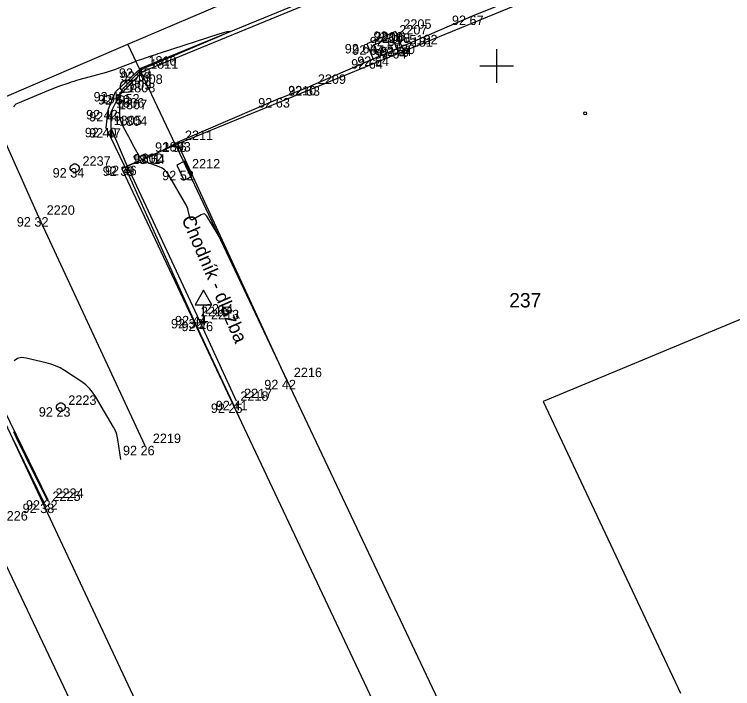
# Model space of a CAD drawing. Extents: x -711081 to -709338, y -1025122 to -1024092.
# Drawn here: x -710739.27 to -710718.02, y -1024943.41 to -1024923.47 of the extents above; entities that cross this region are included whole.
import ezdxf

# ---------------------------------------------------------------- set-up
doc = ezdxf.new("R2010")
doc.units = 0
for name, color, linetype in [('Ex_Minor Contours', 7, 'Continuous'), ('Z_bodove_pole', 7, 'Continuous'), ('Z_bodove_pole_cisla', 7, 'Continuous'), ('Z_bodove_pole_vysky', 7, 'Continuous'), ('Z_body', 7, 'Continuous'), ('Z_body_cisla', 7, 'Continuous'), ('Z_body_vysky_redukovane', 7, 'Continuous'), ('Z_budova', 7, 'Continuous'), ('Z_dopravni_znacky', 7, 'Continuous'), ('Z_hektometricka_sit', 7, 'Continuous'), ('Z_katastr_cisla_stavebni', 7, 'Continuous'), ('Z_katastr_hranice', 7, 'Continuous'), ('Z_katastr_vnitrni_kresba', 7, 'Continuous'), ('Z_katastr_znacky_budov', 7, 'Continuous'), ('Z_komunikace', 7, 'Continuous'), ('Z_komunikace_osa', 7, 'Continuous'), ('Z_obruba', 7, 'Continuous'), ('Z_pilire', 7, 'Continuous'), ('Z_popisy', 7, 'Continuous'), ('Z_rozhranni', 7, 'Continuous'), ('Z_site_vodovod_znaky', 7, 'Continuous'), ('Z_vstupy', 7, 'Continuous')]:
    doc.layers.add(name, color=color, linetype=linetype)

# ---------------------------------------------------------------- blocks, each defined once
blk = doc.blocks.new('POINT_DISPLAY')
blk.add_line((0, 0), (0, 0))
blk = doc.blocks.new('Z666')
for p, q in [((-0.25, 0.13), (-0.25, -0.13)), ((0.25, 0.13), (-0.25, 0.13)), ((0.25, -0.13), (0.25, 0.13)), ((-0.25, -0.13), (0.25, -0.13))]:
    blk.add_line(p, q)
blk = doc.blocks.new('Z614')
for p, q in [((-0.13, 0.03), (-0.1, 0.08)), ((-0.13, -0.03), (-0.13, 0.03)), ((-0.1, 0.08), (-0.08, 0.1)), ((-0.08, 0.1), (-0.03, 0.13)), ((-0.03, 0.13), (0.03, 0.13)), ((0.03, 0.13), (0.08, 0.1)), ((0.08, 0.1), (0.1, 0.08)), ((0.1, 0.08), (0.13, 0.03)), ((0.13, 0.03), (0.13, -0.03)), ((-0.1, -0.08), (-0.13, -0.03)), ((-0.08, -0.1), (-0.1, -0.08)), ((-0.03, -0.13), (-0.08, -0.1)), ((0.03, -0.13), (-0.03, -0.13)), ((0.08, -0.1), (0.03, -0.13)), ((0.1, -0.08), (0.08, -0.1)), ((0.13, -0.03), (0.1, -0.08))]:
    blk.add_line(p, q)
blk = doc.blocks.new('Z527')
for p, q in [((0, 0.93), (-0.25, 0.5)), ((0.25, 0.5), (0, 0.93)), ((-0.25, 0.5), (0.25, 0.5)), ((0, 0), (0, 0.5)), ((-0.13, 0), (0.13, 0))]:
    blk.add_line(p, q)
blk = doc.blocks.new('Z101')
for radius in [0.188, 0.0025]:
    blk.add_circle((0, 0), radius)

msp = doc.modelspace()

# ---------------------------------------------------------------- linework, layer by layer
at = {"layer": 'Ex_Minor Contours'}
for points in [[(-710733.066, -1024930.269), (-710733.573, -1024929.439), (-710733.607, -1024929.398), (-710733.646, -1024929.377), (-710733.69, -1024929.378), (-710733.74, -1024929.399), (-710733.959, -1024929.532), (-710734, -1024929.549), (-710734.033, -1024929.547), (-710734.058, -1024929.525), (-710734.074, -1024929.483), (-710734.121, -1024929.276), (-710734.135, -1024929.225), (-710734.152, -1024929.175), (-710734.174, -1024929.127), (-710734.199, -1024929.081), (-710734.707, -1024928.214), (-710734.76, -1024928.138), (-710734.824, -1024928.074), (-710734.897, -1024928.022), (-710734.981, -1024927.983), (-710735.353, -1024927.841), (-710735.429, -1024927.805), (-710735.495, -1024927.757), (-710735.551, -1024927.698), (-710735.597, -1024927.628), (-710735.768, -1024927.31), (-710735.805, -1024927.24), (-710735.843, -1024927.17), (-710735.88, -1024927.1), (-710735.917, -1024927.03), (-710736.066, -1024926.75), (-710736.098, -1024926.679), (-710736.122, -1024926.605), (-710736.138, -1024926.53), (-710736.144, -1024926.452), (-710736.158, -1024925.921), (-710736.157, -1024925.891), (-710736.152, -1024925.862), (-710736.142, -1024925.834), (-710736.129, -1024925.807), (-710736.066, -1024925.701), (-710736.049, -1024925.676), (-710736.031, -1024925.651), (-710736.012, -1024925.627), (-710735.991, -1024925.604), (-710735.787, -1024925.394), (-710735.758, -1024925.364), (-710735.73, -1024925.335), (-710735.702, -1024925.306), (-710735.673, -1024925.276), (-710735.56, -1024925.159), (-710735.531, -1024925.131), (-710735.499, -1024925.107), (-710735.465, -1024925.086), (-710735.428, -1024925.068), (-710733.193, -1024924.12), (-710732.967, -1024924.02), (-710732.895, -1024923.978), (-710732.977, -1024923.992), (-710733.214, -1024924.064), (-710734.957, -1024924.623), (-710735.026, -1024924.645), (-710735.094, -1024924.667), (-710735.162, -1024924.69), (-710735.23, -1024924.713), (-710735.503, -1024924.805), (-710735.571, -1024924.828), (-710735.638, -1024924.853), (-710735.706, -1024924.878), (-710735.773, -1024924.904), (-710736.184, -1024925.069), (-710736.275, -1024925.104), (-710736.367, -1024925.136), (-710736.46, -1024925.166), (-710736.554, -1024925.193), (-710737.356, -1024925.412), (-710737.432, -1024925.433), (-710737.508, -1024925.456), (-710737.583, -1024925.48), (-710737.658, -1024925.506), (-710737.956, -1024925.611), (-710738.03, -1024925.638), (-710738.104, -1024925.666), (-710738.178, -1024925.695), (-710738.251, -1024925.725), (-710739.169, -1024926.106), (-710739.217, -1024926.132), (-710739.257, -1024926.165), (-710739.289, -1024926.206)], [(-710736.118, -1024936.633), (-710736.202, -1024936.046), (-710736.22, -1024935.949), (-710736.248, -1024935.856), (-710736.285, -1024935.766), (-710736.33, -1024935.68), (-710736.867, -1024934.771), (-710736.95, -1024934.647), (-710737.046, -1024934.534), (-710737.154, -1024934.432), (-710737.274, -1024934.343), (-710737.783, -1024934.007), (-710737.911, -1024933.93), (-710738.045, -1024933.865), (-710738.184, -1024933.813), (-710738.328, -1024933.773), (-710738.914, -1024933.635), (-710739.051, -1024933.622), (-710739.168, -1024933.651), (-710739.267, -1024933.721)], [(-710739.293, -1024935.803), (-710739.208, -1024935.986), (-710739.121, -1024936.168), (-710739.034, -1024936.35), (-710738.945, -1024936.531), (-710738.289, -1024937.859)]]:
    msp.add_lwpolyline(points, dxfattribs=at)
at = {"layer": 'Z_budova'}
for p, q in [((-710717.04, -1024920.03), (-710725.67, -1024923.51)), ((-710725.67, -1024923.51), (-710730.51, -1024925.6)), ((-710731.4, -1024925.95), (-710734.45, -1024927.26)), ((-710734.45, -1024927.26), (-710731.22, -1024934.28))]:
    msp.add_line(p, q, dxfattribs=at)
at = {"layer": 'Z_hektometricka_sit'}
for p, q in [((-710725, -1024924.5), (-710725, -1024925.5)), ((-710725.5, -1024925), (-710724.5, -1024925))]:
    msp.add_line(p, q, dxfattribs=at)
at = {"layer": 'Z_katastr_hranice'}
for p, q in [((-710735.91, -1024924.36), (-710698.09, -1024908.18)), ((-710717.1, -1024920.2), (-710734.5, -1024927.33)), ((-710744.84, -1024928.18), (-710735.91, -1024924.36)), ((-710734.5, -1024927.33), (-710735.91, -1024924.36)), ((-710734.5, -1024927.33), (-710734.37, -1024927.6)), ((-710734.37, -1024927.6), (-710725.49, -1024946.36)), ((-710737.04, -1024944.96), (-710740.05, -1024938.63))]:
    msp.add_line(p, q, dxfattribs=at)
at = {"layer": 'Z_katastr_vnitrni_kresba'}
for p, q in [((-710734.5, -1024927.33), (-710736.09, -1024928.04)), ((-710736.09, -1024928.04), (-710710.637, -1024981.933)), ((-710712.55, -1024930.31), (-710723.62, -1024934.92)), ((-710741.85, -1024930.64), (-710716.679, -1024984.248)), ((-710723.62, -1024934.92), (-710719.56, -1024943.54))]:
    msp.add_line(p, q, dxfattribs=at)
at = {"layer": 'Z_katastr_znacky_budov'}
msp.add_circle((-710722.382, -1024926.4), 0.0437, dxfattribs=at)
at = {"layer": 'Z_komunikace'}
for p, q in [((-710735.52, -1024925.07), (-710726.72, -1024921.45)), ((-710736.27, -1024925.77), (-710735.52, -1024925.07)), ((-710736.49, -1024926.3), (-710736.27, -1024925.77)), ((-710736.55, -1024926.83), (-710736.49, -1024926.3)), ((-710736, -1024927.97), (-710736.55, -1024926.83)), ((-710736, -1024927.97), (-710733.98, -1024932.48)), ((-710738.27, -1024937.84), (-710741.84, -1024930.52)), ((-710733.98, -1024932.48), (-710732.8, -1024934.98))]:
    msp.add_line(p, q, dxfattribs=at)
at = {"layer": 'Z_komunikace_osa'}
for p, q in [((-710738.54, -1024929.47), (-710740.73, -1024924.63)), ((-710735.4, -1024936.23), (-710738.54, -1024929.47))]:
    msp.add_line(p, q, dxfattribs=at)
at = {"layer": 'Z_obruba'}
for p, q in [((-710735.47, -1024925.16), (-710726.67, -1024921.55)), ((-710736.16, -1024925.86), (-710735.47, -1024925.16)), ((-710736.4, -1024926.36), (-710736.16, -1024925.86)), ((-710736.4, -1024926.84), (-710736.4, -1024926.36)), ((-710735.93, -1024927.95), (-710736.4, -1024926.84)), ((-710735.93, -1024927.95), (-710733.86, -1024932.39)), ((-710738.37, -1024937.94), (-710741.97, -1024930.6)), ((-710733.86, -1024932.39), (-710732.7, -1024934.9))]:
    msp.add_line(p, q, dxfattribs=at)
at = {"layer": 'Z_rozhranni'}
for p, q in [((-710727.99, -1024923.98), (-710728.84, -1024924.35)), ((-710727.99, -1024923.98), (-710727.8, -1024924.43)), ((-710728.1, -1024924.14), (-710728.62, -1024924.39)), ((-710728.1, -1024924.14), (-710727.95, -1024924.5)), ((-710728.84, -1024924.35), (-710728.65, -1024924.8)), ((-710728.62, -1024924.39), (-710728.47, -1024924.72)), ((-710735.1, -1024927.61), (-710734.45, -1024927.26)), ((-710735.93, -1024927.95), (-710735.1, -1024927.61))]:
    msp.add_line(p, q, dxfattribs=at)
at = {"layer": 'Z_vstupy'}
msp.add_line((-710731.4, -1024925.95), (-710730.51, -1024925.6), dxfattribs=at)

# ---------------------------------------------------------------- block references
at = {"layer": 'Z_bodove_pole'}
msp.add_blockref('Z101', (-710735.94, -1024925.6), dxfattribs=at)
at = {"layer": 'Z_body'}
for p in [(-710725.67, -1024923.51), (-710727.99, -1024923.98), (-710728.1, -1024924.14), (-710728.84, -1024924.35), (-710728.62, -1024924.39), (-710727.95, -1024924.5), (-710727.8, -1024924.43), (-710728.47, -1024924.72), (-710728.65, -1024924.8), (-710735.52, -1024925.07), (-710735.47, -1024925.16), (-710735.94, -1024925.6), (-710730.51, -1024925.6), (-710736.27, -1024925.77), (-710736.16, -1024925.86), (-710731.4, -1024925.95), (-710736.49, -1024926.3), (-710736.4, -1024926.36), (-710736.55, -1024926.83), (-710736.4, -1024926.84), (-710734.45, -1024927.26), (-710735.1, -1024927.61), (-710735.93, -1024927.95), (-710737.48, -1024928.02), (-710736, -1024927.97), (-710734.24, -1024928.1), (-710738.54, -1024929.47), (-710733.86, -1024932.39), (-710733.98, -1024932.48), (-710733.67, -1024932.56), (-710731.22, -1024934.28), (-710732.7, -1024934.9), (-710737.89, -1024935.09), (-710732.8, -1024934.98), (-710735.4, -1024936.23), (-710738.37, -1024937.94), (-710738.27, -1024937.84)]:
    msp.add_blockref('POINT_DISPLAY', p, dxfattribs=at)
at = {"layer": 'Z_dopravni_znacky'}
msp.add_blockref('Z527', (-710733.67, -1024932.56), dxfattribs=at)
at = {"layer": 'Z_pilire', "rotation": -64.8}
msp.add_blockref('Z666', (-710734.24, -1024928.1), dxfattribs=at)
at = {"layer": 'Z_site_vodovod_znaky'}
for p in [(-710737.48, -1024928.02), (-710737.89, -1024935.09)]:
    msp.add_blockref('Z614', p, dxfattribs=at)

# ---------------------------------------------------------------- texts
at = {"layer": 'Z_bodove_pole_cisla'}
msp.add_text('4008', height=0.28, dxfattribs=at).set_placement((-710735.71, -1024925.53))
at = {"layer": 'Z_bodove_pole_vysky'}
msp.add_text('192,52', height=0.28, dxfattribs=at).set_placement((-710736.707, -1024926.11))
at = {"layer": 'Z_body_cisla'}
for s, p in [('2205', (-710727.76, -1024923.9)), ('2207', (-710727.88, -1024924.07)), ('2206', (-710728.61, -1024924.28)), ('2208', (-710728.39, -1024924.32)), ('5182', (-710727.58, -1024924.36)), ('5181', (-710727.72, -1024924.43)), ('5179', (-710728.42, -1024924.73)), ('5180', (-710728.25, -1024924.65)), ('1810', (-710735.3, -1024924.99)), ('1811', (-710735.25, -1024925.08)), ('2209', (-710730.29, -1024925.53)), ('1809', (-710736.05, -1024925.7)), ('1808', (-710735.93, -1024925.78)), ('2210', (-710731.17, -1024925.87)), ('1806', (-710736.26, -1024926.23)), ('1807', (-710736.17, -1024926.28)), ('1805', (-710736.33, -1024926.75)), ('1804', (-710736.17, -1024926.77)), ('2211', (-710734.22, -1024927.19)), ('1803', (-710734.88, -1024927.53)), ('2237', (-710737.25, -1024927.95)), ('1801', (-710735.78, -1024927.9)), ('1802', (-710735.71, -1024927.87)), ('2212', (-710734.01, -1024928.03)), ('2220', (-710738.31, -1024929.4)), ('2215', (-710733.75, -1024932.4)), ('2214', (-710733.63, -1024932.32)), ('2213', (-710733.45, -1024932.49)), ('2216', (-710731, -1024934.2)), ('2217', (-710732.47, -1024934.82)), ('2223', (-710737.67, -1024935.02)), ('2218', (-710732.58, -1024934.9)), ('2219', (-710735.17, -1024936.15)), ('2224', (-710738.05, -1024937.77)), ('2225', (-710738.14, -1024937.86)), ('2226', (-710739.7, -1024938.44))]:
    msp.add_text(s, height=0.28, dxfattribs=at).set_placement(p)
at = {"layer": 'Z_body_vysky_redukovane'}
for s, p in [('92 67', (-710726.323, -1024923.79)), ('92 66', (-710728.643, -1024924.26)), ('92 64', (-710729.493, -1024924.63)), ('92 64', (-710728.753, -1024924.42)), ('92 64', (-710729.273, -1024924.67)), ('92 64', (-710728.603, -1024924.78)), ('92 64', (-710728.453, -1024924.71)), ('92 64', (-710729.123, -1024925)), ('92 64', (-710729.303, -1024925.08)), ('92 48', (-710736.173, -1024925.35)), ('92 54', (-710736.123, -1024925.44)), ('92 63', (-710731.163, -1024925.88)), ('92 45', (-710736.923, -1024926.05)), ('92 50', (-710736.79, -1024926.14)), ('92 63', (-710732.053, -1024926.23)), ('92 42', (-710737.143, -1024926.58)), ('92 49', (-710737.053, -1024926.64)), ('92 40', (-710737.18, -1024927.11)), ('92 47', (-710737.053, -1024927.12)), ('92 56', (-710735.103, -1024927.54)), ('92 54', (-710735.753, -1024927.89)), ('92 46', (-710736.583, -1024928.23)), ('92 34', (-710738.133, -1024928.3)), ('92 39', (-710736.653, -1024928.25)), ('92 52', (-710734.893, -1024928.38)), ('92 32', (-710739.193, -1024929.75)), ('92 44', (-710734.513, -1024932.67)), ('92 32', (-710734.633, -1024932.76)), ('92 46', (-710734.323, -1024932.84)), ('92 42', (-710731.873, -1024934.56)), ('92 41', (-710733.307, -1024935.18)), ('92 23', (-710738.543, -1024935.37)), ('92 25', (-710733.453, -1024935.26)), ('92 26', (-710736.053, -1024936.51)), ('92 38', (-710739.023, -1024938.22)), ('92 22', (-710738.923, -1024938.12))]:
    msp.add_text(s, height=0.28, dxfattribs=at).set_placement(p)
at = {"layer": 'Z_katastr_cisla_stavebni'}
msp.add_text('237', height=0.425, dxfattribs=at).set_placement((-710724.628, -1024932.14))
at = {"layer": 'Z_popisy'}
msp.add_text('Chodník - dlažba', height=0.4, rotation=293.4, dxfattribs=at).set_placement((-710734.33, -1024929.52))

doc.saveas('drawing.dxf')
